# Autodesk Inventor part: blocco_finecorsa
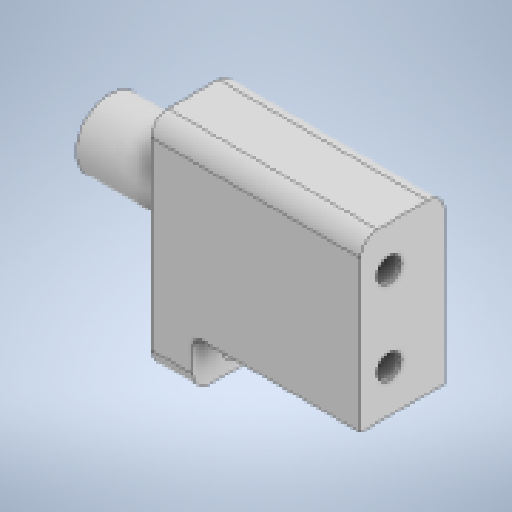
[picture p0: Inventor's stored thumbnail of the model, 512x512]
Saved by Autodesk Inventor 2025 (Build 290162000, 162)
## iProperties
Created: 2026-03
Part Number: blocco_finecorsa
Material: Generico
Document SubType Name: Modeling
Designer: Ryzen5700u
Density: 1 g/cm^3
Appearance: Default
Author: Ryzen5700u
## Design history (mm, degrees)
sketch "Schizzo1"
  geometry: L1 (10, 5)-(-10, 5); L2 (-10, 5)-(-10, -5); L3 (-10, -5)-(10, -5); L4 (10, -5)-(10, 5); L5 (10, 5)-(-10, -5); L6 (-10, 5)-(10, -5); 1 further point
  constraints: 12 end point, 2 midpoint, 2 parallel, 1 horizontal, 1 perpendicular
  dimensions: "d0" = 20 distance of L3.end L2.end; "d1" = 10 distance of L2.end L1.end
extrude "Estrusione1" new body sketch "Schizzo1" distance "d2" = 27; taper "d3" = 0 deg
sketch "Schizzo2"
  geometry: C1 r 4 at (0, 1); 1 further point
  constraints: 1 centre point
  dimensions: "d4" = 8 diameter of C1; "d5" = 1 distance of point (0, 0) C1.centre
extrude "Estrusione2" join sketch "Schizzo2" distance "d6" = 10; taper "d7" = 0 deg
sketch "Schizzo3"
  geometry: C1 r 1.25 at (-1.6, 5.125) reference; C2 r 1.25 at (-1.6, -4.875) reference; 1 further point
hole "Foro1" sketch "Schizzo3" at (-1.6, 5.125), (-1.6, -4.875) diameter "d9" = 2.9; stored, may be unused: countersink angle "d13" = 90 deg, drill point angle "d15" = 118 deg; dims "d10" = 6, "d11" = 5.5, "d12" = 2.9, "d14" = 8
sketch "Schizzo4"
  geometry: L1 (5, -10)-(-5, -10) reference; L2 (5, 10)-(5, -10) reference; L3 (-5, 10)-(5, 10) reference; L4 (-5, -10)-(-5, 10) reference; L5 (5, -10)-(-5, -10) reference; L6 (5, -10)-(-5, -10); L7 (-5, -10)-(-5, -16); L8 (-5, -16)-(5, -16); L9 (5, -16)-(5, -10); C1 r 4 at (0, 1) reference; 2 further points
  constraints: 8 end point, 2 parallel, 1 horizontal, 1 perpendicular
  dimensions: "d16" = 6 distance of L7.end L6.end
extrude "Estrusione3" join sketch "Schizzo4" distance "d17" = 5; taper "d18" = 0 deg
fillet "Raccordo2" dims "d19" = 1
sketch "Schizzo5"
  geometry: L1 (-5, -16)-(5, -16) reference; 2 further points
  dimensions: "d27" = 2.5 distance from line of L1 point (0, -13.5)
hole "Foro2" sketch "Schizzo5" at (0, -13.5) diameter "d20" = 2.9; stored, may be unused: countersink angle "d24" = 90 deg, drill point angle "d26" = 118 deg; dims "d21" = 6, "d22" = 4, "d23" = 2, "d25" = 8
fillet "Raccordo3" dims "d28" = 2
node "Solido1"
node "Riferimento1"
node "Riferimento2"
node "Linea chiusa proiettata1"
